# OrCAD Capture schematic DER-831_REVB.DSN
size Custom; title: DER 831; rev: A
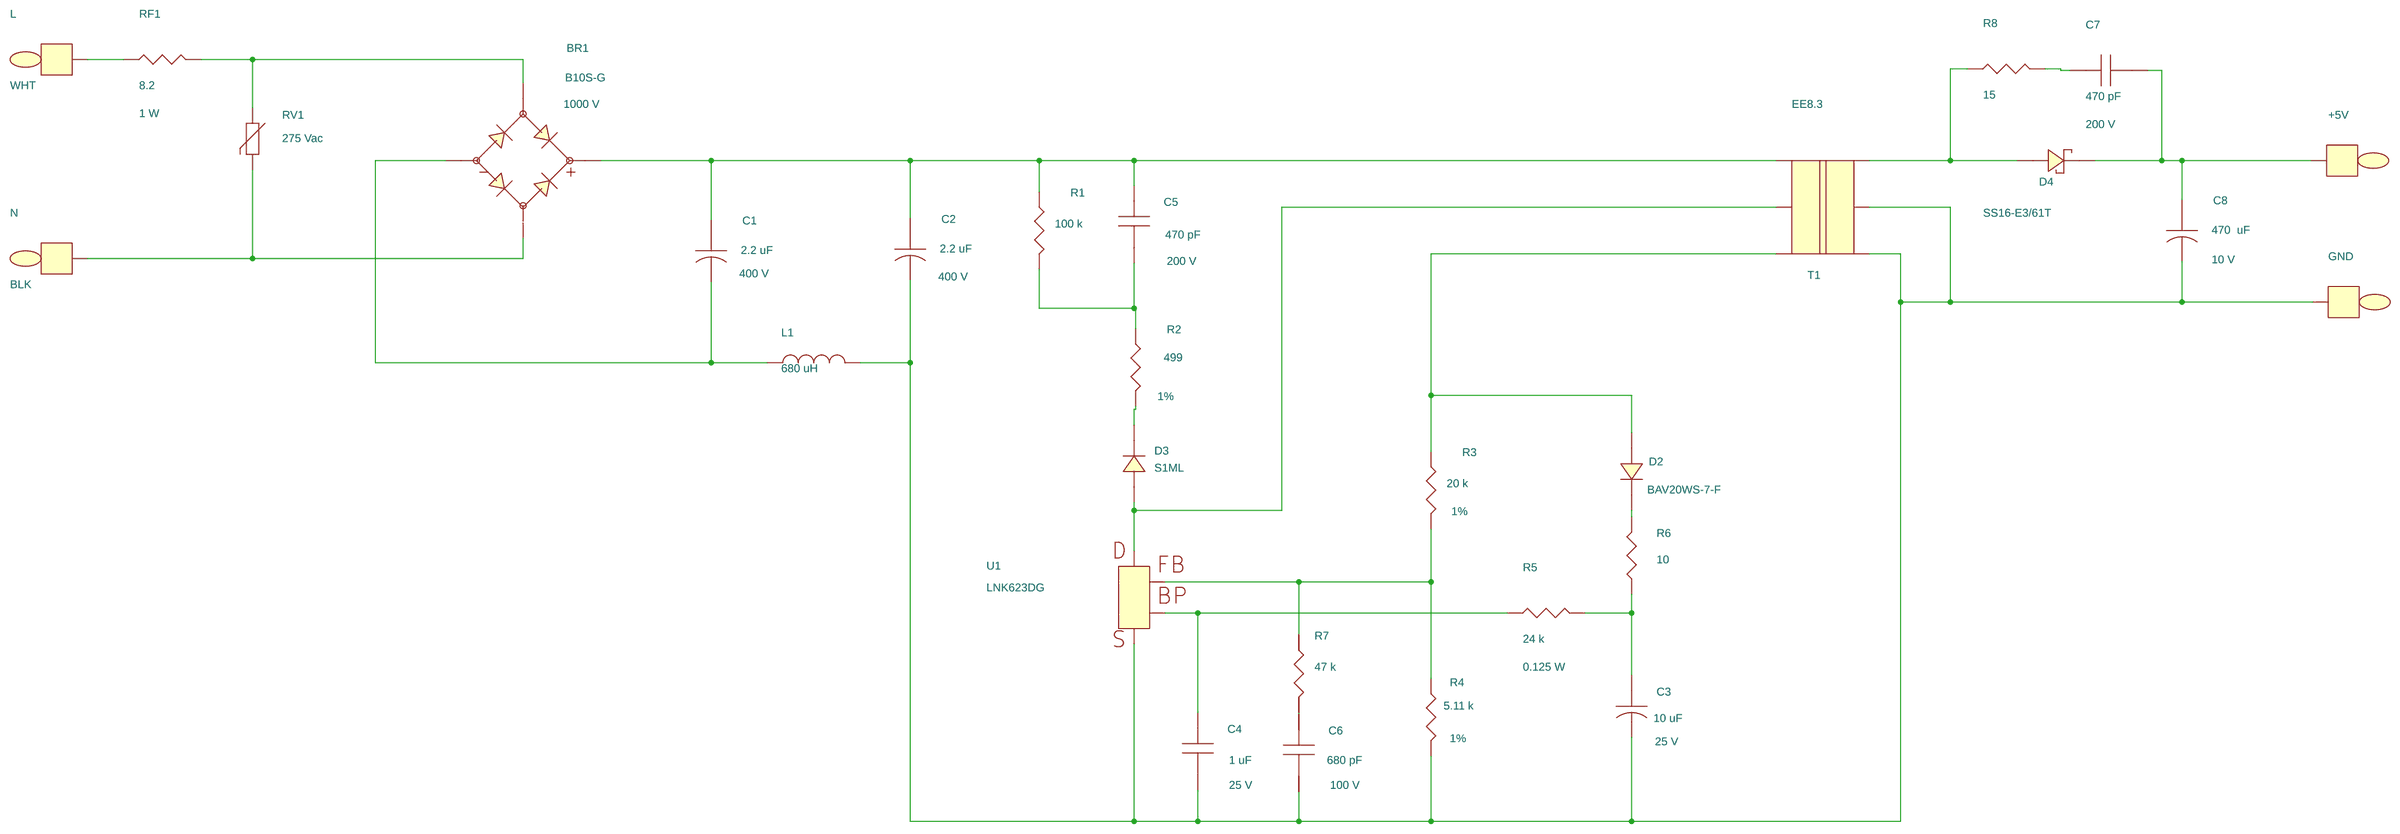
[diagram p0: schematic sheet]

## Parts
+5V  RED  [pitpkeystone100x100]
BR1  B10S-G  [pismsoic4]
C1  2.2 uF  [pipolcapcyld250ls100030]
C2  2.2 uF  [pipolcapcyld250ls100030]
C3  10 uF  [pipolcapclyd5mmls2mm025]
C4  1 uF  [pismc0805]
C5  470 pF  [pismc0805]
C6  680 pF  [pismc0603]
C7  470 pF  [pismc0805]
C8  470  uF  [pipolcapclyd320ls140030]
D2  BAV20WS-7-F  [pismdsod323]
D3  S1ML  [pi_sm_sod-123_12]
D4  SS16-E3/61T  [pismdo214ac12]
GND  BLK  [pitpkeystone100x100]
L  WHT  [pitpkeystone100x100]
L1  680 uH  [pichoketokinvd216h413ls098d030]
N  BLK  [pitpkeystone100x100]
R1  100 k  [pismr0805]
R2  499  [pismr1206]
R3  20 k  [pismr0603]
R4  5.11 k  [pismr0603]
R5  24 k  [pi18wvresd80ls100d030]
R6  10  [pismr0603]
R7  47 k  [pismr0603]
R8  15  [pismr0805]
RF1  8.2  [pi12wresd180ls575040]
RV1  275 Vac  [pi_disc276x181_ls200x83d040]
T1  EE8.3  [pi_bobbin_ee8_3H6p]
U1  LNK623DG  [pismso8dnshort5678]

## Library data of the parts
+5V = TESTPOINT: Part Number: 35-00080-00
BR1 = DIODE_BRIDGE_~~+-: ALT_SYMBOLS: pi_sm_soic4_slot; Disp_Voltage: 1000 V; FPLIST: pismsoic4,pi_sm_soic4_slot; Part Number: 15-00818-00
C1 C2 = CAP_POL: ALT_SYMBOLS: pipolcapcyld250ls100030h; Disp_Voltage: 400 V; FPLIST: pipolcapcyld250ls100030,pipolcapcyld250ls100030h; Part Number: 20-01008-00; Voltage: 400 V
C3 = CAP_POL: Disp_Voltage: 25 V; Part Number: 20-09124-00; Voltage: 25 V
C4 = CAP_NP: Disp_Voltage: 25 V; Part Number: 20-09171-00; Voltage: 25 V
C5 C7 = CAP_NP: Disp_Voltage: 200 V; Part Number: 20-01187-00; Voltage: 200 V
C6 = CAP_NP: Disp_Voltage: 100 V; Part Number: 20-08597-00; Voltage: 100 V
C8 = CAP_POL: ALT_SYMBOLS: pipolcapclyd320ls140030430h; Disp_Voltage: 10 V; FPLIST: pipolcapclyd320ls140030,pipolcapclyd320ls140030430h; Part Number: 20-00003-00; Voltage: 10 V
D2 = DIODE: Part Number: 15-00712-00
D3 = DIODE: Part Number: 15-01027-00
D4 = DIODE_SCHOTTKY: Part Number: 15-00977-00
GND N = TESTPOINT: Part Number: 35-00079-00
L = TESTPOINT: Part Number: 35-00081-00
L1 = INDUCTOR: Part Number: 30-00019-00
R1 = R: Part Number: 05-01567-00
R2 = R: Disp_Tol: 1%; Part Number: 05-00164-00
R3 = R: Disp_Tol: 1%; Part Number: 05-03213-00
R4 = R: Disp_Tol: 1%; Part Number: 05-01146-00
R5 = R: ALT_SYMBOLS: pi18wresd080ls300d030; Disp_Power: 0.125 W; FPLIST: pi18wvresd80ls100d030,pi18wresd080ls300d030; Part Number: 05-02370-00
R6 = R: Part Number: 05-01640-00
R7 = R: Part Number: 05-01728-00
R8 = R: Part Number: 05-01475-00
RF1 = RF: ALT_SYMBOLS: pi1wvresd120ls200d040; Disp_Power: 1 W; FPLIST: pi12wresd180ls575040,pi1wvresd120ls200d040; Part Number: 05-06353-00
RV1 = VARISTOR: Part Number: 85-00040-00
T1 = BEE8_3_6P: Part Number: 25-01154-00
U1 = LNK62X: Part Number: 10-00300-00

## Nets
SOURCE: U1.6(SOURCE) U1.7(SOURCE) U1.8(SOURCE)
N02548: BR1.3 C1.1 C2.1 C5.1 R1.1 T1.3
N02667: C2.2 C3.2 C4.2 C6.2 C8.2 GND.1 L1.2 R4.2 T1.5 T1.6 U1.5(S)
N02674: BR1.4 C1.2 L1.1
N03548: C4.1 R5.1 U1.2(BP)
N03639: R3.2 R4.1 R7.1 U1.1(FB)
N04459: C3.1 R5.2 R6.1
N04496: D2.1 R6.2
N04748: D3.2 T1.2 U1.4(D)
N04766: D2.2 R3.1 T1.1
N04877: D4.2 R8.1 T1.4
N04912: C7.1 R8.2
N04991: +5V.1 C7.2 C8.1 D4.1
N06108: BR1.1 RF1.2 RV1.1
N06154: L.1 RF1.1
N06177: BR1.2 N.1 RV1.2
N12152: C5.2 R1.2 R2.1
N12184: D3.1 R2.2
N16271: C6.1 R7.2
